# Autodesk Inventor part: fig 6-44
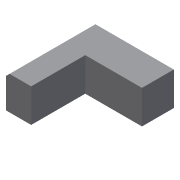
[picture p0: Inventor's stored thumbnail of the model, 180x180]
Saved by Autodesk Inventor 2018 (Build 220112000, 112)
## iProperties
Created: 2010-08
Part Number: fig 6-44
Document SubType Name: Modeling
Designer: CADSoft
Density: 1 g/cm^3
Material: Generic
Appearance: Default
Author: CADSoft
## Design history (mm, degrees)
sketch "Sketch1"
  geometry: L1 (-33.983, 0)-(-48.97, 0); L2 (-48.97, 0)-(-48.97, 51.503); L3 (-48.97, 51.503)-(0, 51.503); L4 (0, 51.503)-(0, 32.411); L5 (-33.983, 0)-(-33.983, 32.411); L6 (-33.983, 32.411)-(0, 32.411); 1 further point
  constraints: 12 end point, 3 parallel, 2 perpendicular, 1 horizontal
extrude "Extrusion1" new body sketch "Sketch1" distance "d0" = 20; taper "d1" = 0 deg
chamfer "Chamfer1" distance "d2" = 2; stored, may be unused: second distance "d3" = 2, angle "d4" = 45 deg
body "Solid1"
